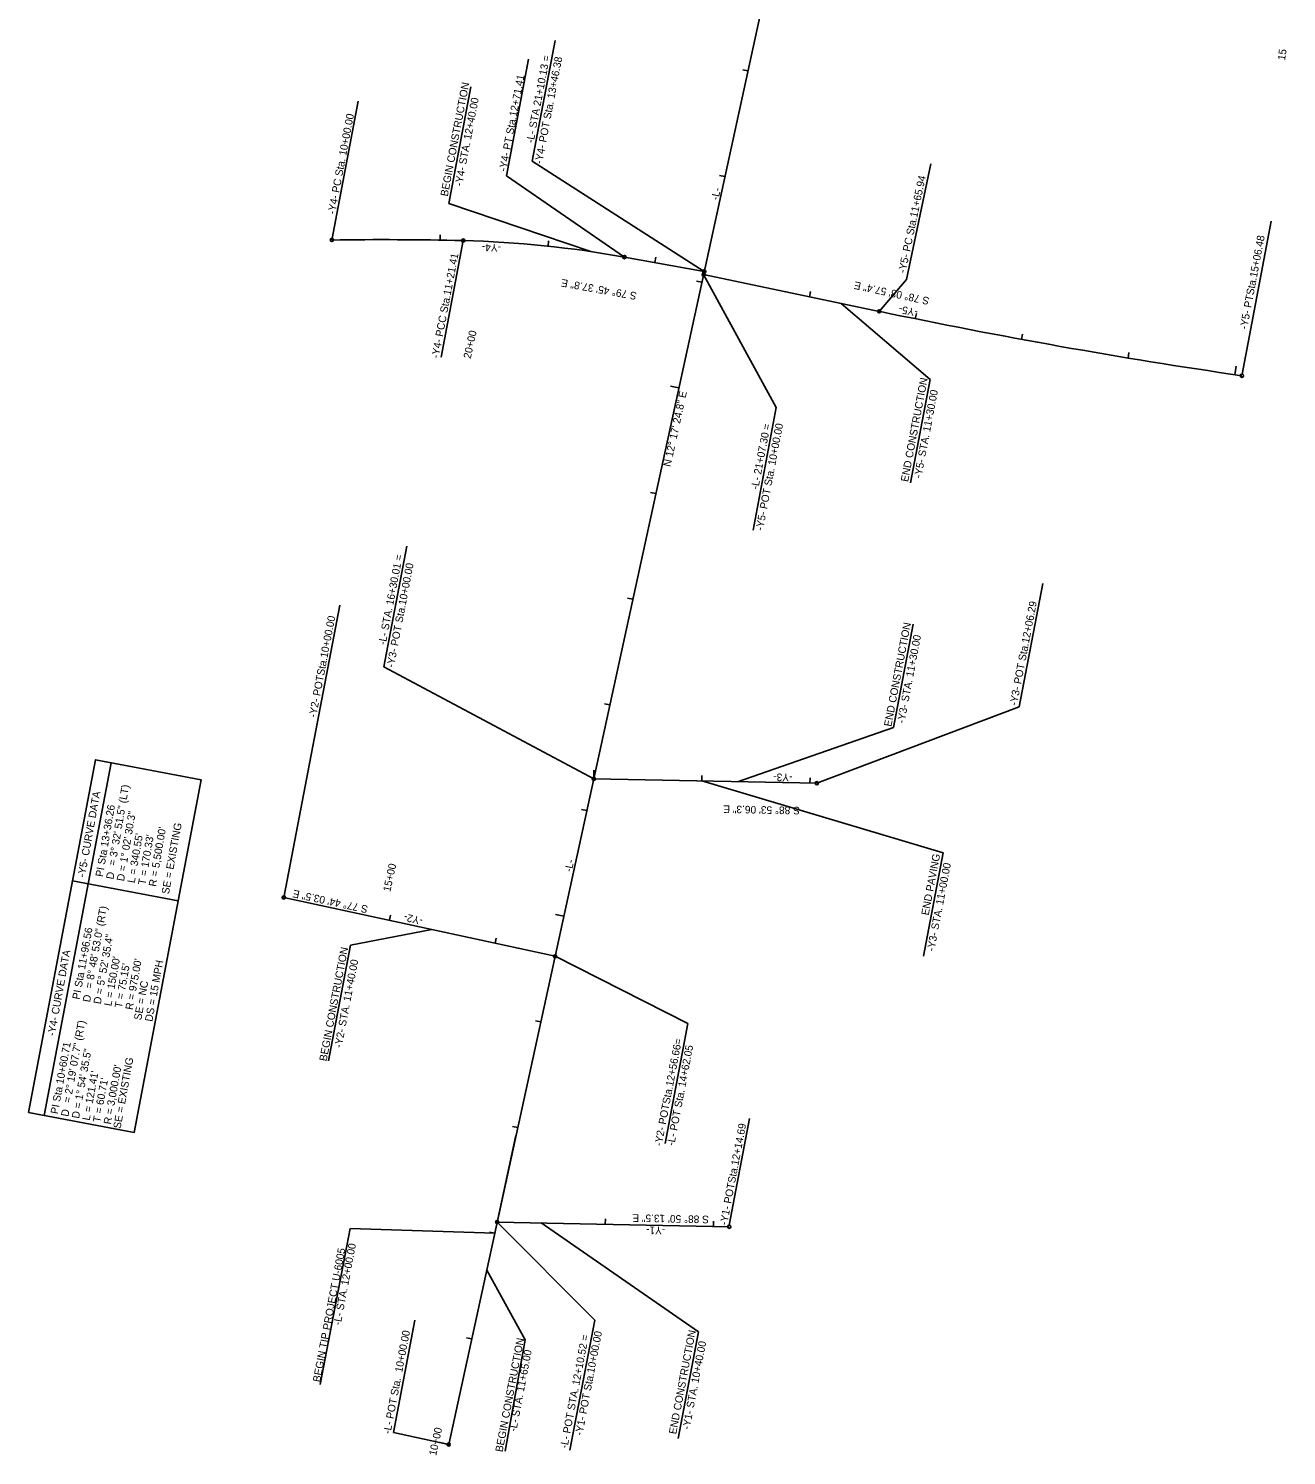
# Model space of a CAD drawing. Extents: x 1615712 to 1617175, y 899615 to 904865.
# Drawn here: x 1615800 to 1616963, y 899615 to 900935 of the extents above; entities that cross this region are included whole.
import ezdxf

# ---------------------------------------------------------------- set-up
doc = ezdxf.new("R2010")
doc.units = 0
for name, color, linetype in [('Prop Horizontal Alignment', 7, 'Continuous'), ('Prop Horizontal Alignment Curve and Spiral Data', 7, 'Continuous'), ('Prop Horizontal Alignment Direction Label', 7, 'Continuous'), ('Prop Horizontal Alignment Station Label', 7, 'Continuous'), ('Prop Horizontal Alignment Tick Label', 7, 'Continuous'), ('Prop Horizontal Alignment Tick Large', 7, 'Continuous'), ('Prop Horizontal Alignment Tick Small', 7, 'Continuous'), ('Scratch_Level_0', 7, 'Continuous')]:
    doc.layers.add(name, color=color, linetype=linetype)

msp = doc.modelspace()

# ---------------------------------------------------------------- linework, layer by layer
at = {"layer": 'Prop Horizontal Alignment'}
for p, q in [((1616188.3, 899625.3), (1616593.6, 901486.1)), ((1616188.3, 899625.3), (1616593.6, 901486.1)), ((1616230.8, 899820.7), (1616250.5, 899911)), ((1616233.1, 899831), (1616447.7, 899826.6))]:
    msp.add_line(p, q, dxfattribs=at)
at = {"layer": 'Prop Horizontal Alignment Curve and Spiral Data'}
for p, q in [((1615840.5, 900146.6), (1615938.3, 900128)), ((1616409.5, 900014.6), (1616388.5, 899903.7)), ((1616137.3, 899636.4), (1616157.1, 899740.3))]:
    msp.add_line(p, q, dxfattribs=at)
for points in [[(1615799.8, 899932.3), (1615861.8, 900258.5), (1615959.5, 900239.9), (1615897.6, 899913.8)], [(1615799.8, 899932.3), (1615861.8, 900258.5), (1615876.2, 900255.7), (1615814.3, 899929.6)]]:
    msp.add_lwpolyline(points, close=True, dxfattribs=at)
at = {"layer": 'Prop Horizontal Alignment Station Label'}
for p, q in [((1616265.4, 900812.1), (1616286.6, 900923.4)), ((1616241.6, 900798.3), (1616262.1, 900906.2)), ((1616188.3, 900772.8), (1616208.8, 900880.7)), ((1616080.6, 900740.5), (1616104.7, 900867.4)), ((1616265.4, 900812.1), (1616424.6, 900710)), ((1616611.5, 900702.5), (1616633.9, 900809.5)), ((1616350.8, 900723.3), (1616241.6, 900798.3)), ((1616188.3, 900772.8), (1616319.8, 900728.4)), ((1616921.8, 900615), (1616948.7, 900756.4)), ((1616181.2, 900630.7), (1616201.7, 900738.5)), ((1616350.8, 900723.3), (1616424.6, 900710)), ((1616350.8, 900723.3), (1616424.6, 900710)), ((1616491.2, 900584.1), (1616424, 900707.2)), ((1616424, 900707.2), (1616586.4, 900673.1)), ((1616586.4, 900673.1), (1616611.5, 900702.5)), ((1616633.5, 900610), (1616551.2, 900680.5)), ((1616615.3, 900514.5), (1616633.5, 900610)), ((1616469.8, 900470.9), (1616491.2, 900584.1)), ((1616128.4, 900344.5), (1616149.5, 900456)), ((1616715.6, 900307.5), (1616737.6, 900421.3)), ((1616036.1, 900132.7), (1616087.6, 900401.3)), ((1616599.5, 900288.3), (1616617.7, 900383.9)), ((1616128.4, 900344.5), (1616322.4, 900240.8)), ((1616715.6, 900307.5), (1616528.6, 900236.8)), ((1616599.5, 900288.3), (1616455.4, 900238.2)), ((1616322.4, 900240.8), (1616528.6, 900236.8)), ((1616645.5, 900172.4), (1616422.3, 900238.9)), ((1616627.3, 900076.9), (1616645.5, 900172.4)), ((1616035.8, 900131.2), (1616286.6, 900076.7)), ((1616097.5, 900087.1), (1616172.6, 900101.5)), ((1616077.2, 899980.2), (1616097.5, 900087.1)), ((1616286.6, 900076.7), (1616409.5, 900014.6)), ((1616447.7, 899828.1), (1616466.5, 899926.7)), ((1616323.3, 899740.4), (1616233.1, 899831)), ((1616419.1, 899729.5), (1616273.7, 899830.2)), ((1616259, 899722), (1616223.4, 899786.5)), ((1616300.4, 899620.2), (1616323.3, 899740.4)), ((1616400.4, 899631), (1616419.1, 899729.5)), ((1616240.5, 899619), (1616259, 899722)), ((1616186.8, 899625.6), (1616137.3, 899636.4))]:
    msp.add_line(p, q, dxfattribs=at)
msp.add_lwpolyline([(1616230.8, 899820.7), (1616097.2, 899825), (1616069.5, 899680.7)], dxfattribs=at)
for centre in [(1616080.3, 900739.1), (1616201.7, 900738.5), (1616350.8, 900723.3), (1616424, 900707.2), (1616424.6, 900710), (1616586.4, 900673.1), (1616921.6, 900613.5), (1616322.4, 900240.8), (1616528.6, 900236.8), (1616035.8, 900131.2), (1616286.6, 900076.7), (1616233.1, 899831), (1616447.7, 899826.6), (1616188.3, 899625.3)]:
    msp.add_circle(centre, 1.5, dxfattribs=at)
for centre, radius, start, end in [((1616127.1, 897739.4), 3000, 88.5752, 90.894), ((1616177.5, 899763.8), 975, 79.7605, 88.5752), ((1616177.5, 899763.8), 975, 79.7605, 88.5752), ((1617715.9, 906055.9), 5500, 258.1493, 261.6969), ((1617715.9, 906055.9), 5500, 258.1493, 261.6969)]:
    msp.add_arc(centre, radius, start, end, dxfattribs=at)
at = {"layer": 'Prop Horizontal Alignment Tick Large'}
for p, q in [((1616080.3, 900739.1), (1616081.8, 900746.9)), ((1616424, 900707.2), (1616425.6, 900715)), ((1616915.2, 900614.5), (1616916.4, 900622.4)), ((1616401.1, 900602.3), (1616393.3, 900604)), ((1616322.4, 900240.8), (1616322.5, 900248.8)), ((1616035.8, 900131.2), (1616037.3, 900139.1)), ((1616294.7, 900113.8), (1616286.9, 900115.5)), ((1616188.3, 899625.3), (1616180.4, 899627))]:
    msp.add_line(p, q, dxfattribs=at)
at = {"layer": 'Prop Horizontal Alignment Tick Small'}
for p, q in [((1616465, 900895.5), (1616460.1, 900896.5)), ((1616443.7, 900797.8), (1616438.8, 900798.8)), ((1616180.3, 900739), (1616180.4, 900744)), ((1616280.1, 900733.4), (1616280.6, 900738.4)), ((1616378.9, 900718.2), (1616379.8, 900723.1)), ((1616422.4, 900700.1), (1616417.5, 900701.1)), ((1616521.8, 900686.6), (1616522.9, 900691.5)), ((1616619.7, 900666.2), (1616620.7, 900671.1)), ((1616717.9, 900647.2), (1616718.8, 900652.1)), ((1616816.4, 900629.9), (1616817.2, 900634.9)), ((1616379.8, 900504.6), (1616374.9, 900505.7)), ((1616358.5, 900406.9), (1616353.7, 900408)), ((1616337.3, 900309.2), (1616332.4, 900310.3)), ((1616422.3, 900238.9), (1616422.4, 900243.9)), ((1616522.3, 900236.9), (1616522.4, 900241.9)), ((1616316, 900211.5), (1616311.1, 900212.6)), ((1616133.5, 900110), (1616134.6, 900114.9)), ((1616231.2, 900088.8), (1616232.3, 900093.6)), ((1616273.4, 900016.1), (1616268.5, 900017.2)), ((1616252.1, 899918.4), (1616247.2, 899919.4)), ((1616333, 899828.9), (1616333.2, 899833.9)), ((1616230.8, 899820.7), (1616225.9, 899821.7)), ((1616433, 899826.9), (1616433.1, 899831.9)), ((1616209.5, 899723), (1616204.7, 899724))]:
    msp.add_line(p, q, dxfattribs=at)
at = {"layer": 'Scratch_Level_0'}
for p, q in [((1616188.3, 899625.3), (1616593.6, 901486.1)), ((1616233.1, 899831), (1616447.7, 899826.6))]:
    msp.add_line(p, q, dxfattribs=at)

# ---------------------------------------------------------------- texts
at = {"layer": 'Prop Horizontal Alignment Curve and Spiral Data'}
for s, rotation, p in [('= 3%%d 32\' 51.5" (LT)', 80.3102, (1615880.2, 900160.2)), ('-Y5- CURVE DATA', 79.6716, (1615851.9, 900149.3)), ('PI Sta 13+36.26', 80.3102, (1615868.5, 900149.8)), ('D = 1%%d 02\' 30.3"', 80.3102, (1615888.1, 900145.8)), ("L = 340.55'", 80.3102, (1615898, 900144.1)), ("T = 170.33'", 80.3102, (1615907.9, 900142.4)), ("R = 5,500.00'", 80.3102, (1615917.7, 900140.8)), ('SE = EXISTING', 79.6716, (1615929.6, 900133.8)), ('D', 80.3102, (1615878.3, 900147.5)), ('= 8%%d 48\' 53.0" (RT)', 79.6721, (1615858.7, 900046.6)), ('PI Sta 11+96.56', 79.6721, (1615847, 900036.4)), ('D = 5%%d 52\' 35.4"', 79.6721, (1615866.6, 900032.1)), ('-Y4- CURVE DATA', 79.6716, (1615824.1, 900002.6)), ("L = 150.00'", 79.6721, (1615876.4, 900030.3)), ("R = 975.00'", 79.6721, (1615896.1, 900026.8)), ('DS = 15 MPH', 79.6716, (1615914.2, 900015.9)), ("T = 75.15'", 79.6721, (1615886.2, 900028.5)), ('SE = NC', 79.6716, (1615904, 900017.3)), ('D', 79.6721, (1615856.7, 900033.9)), ('= 2%%d 19\' 07.7" (RT)', 79.6716, (1615838.6, 899940.8)), ('PI Sta 10+60.71', 79.6716, (1615826.9, 899930.5)), ('D = 1%%d 54\' 35.5"', 79.6716, (1615846.5, 899926.3)), ('SE = EXISTING', 79.6716, (1615884.9, 899916.9)), ("L = 121.41'", 79.6716, (1615856.3, 899924.5)), ("R = 3,000.00'", 79.6716, (1615876, 899920.9)), ("T = 60.71'", 79.6716, (1615866.1, 899922.7)), ('D', 79.6716, (1615836.6, 899928.1))]:
    msp.add_text(s, height=7, rotation=rotation, dxfattribs=at).set_placement(p)
at = {"layer": 'Prop Horizontal Alignment Direction Label'}
for s, rotation, p in [('S 79%%d 45\' 37.8" E', 169.7605, (1616362.6, 900690.5)), ('S 78%%d 08\' 57.4" E', 167.719, (1616633.1, 900685.8)), ('N 12%%d 17\' 24.8" E', 77.7098, (1616393.4, 900528.9)), ('S 88%%d 53\' 06.3" E', 178.8851, (1616513, 900214.9)), ('S 77%%d 44\' 03.5" E', 167.7343, (1616114.1, 900123.3)), ('S 88%%d 50\' 13.5" E', 178.8371, (1616428.9, 899836.8))]:
    msp.add_text(s, height=7, rotation=rotation, dxfattribs=at).set_placement(p)
at = {"layer": 'Prop Horizontal Alignment Station Label'}
for s, rotation, p in [('-L- STA 21+10.13 =', 79.2494, (1616266.7, 900828.3)), ('-Y4- POT Sta. 13+46.38', 79.2494, (1616274.6, 900809)), ('-Y4- PT Sta.12+71.41', 79.2494, (1616241.5, 900802.1)), ('BEGIN CONSTRUCTION', 79.2494, (1616187.4, 900779)), ('-Y4- STA. 12+40.00', 79.2494, (1616200.7, 900788.5)), ('-Y4- PC Sta. 10+00.00', 79.2494, (1616083.2, 900762.4)), ('-Y5- PC Sta.11+65.94', 78.1493, (1616610.6, 900708)), ('-Y5- PTSta.15+06.48', 79.2494, (1616926.4, 900656)), ('-Y4- PCC Sta.11+21.41', 79.2494, (1616179, 900629.3)), ('END CONSTRUCTION', 79.2494, (1616613, 900515)), ('-Y5- STA. 11+30.00', 79.2494, (1616625.2, 900518.3)), ('-L- 21+07.30 =', 79.2494, (1616474.5, 900508.1)), ('-Y5- POT Sta. 10+00.00', 79.2494, (1616478.8, 900469.9)), ('-L- STA. 16+30.01 =', 79.2494, (1616130, 900364.2)), ('-Y3- POT Sta.10+00.00', 79.2494, (1616137.6, 900343.3)), ('-Y3- POT Sta.12+06.29', 79.0894, (1616713.6, 900308.1)), ('-Y2- POTSta.10+00.00', 79.1535, (1616065.6, 900297.1)), ('END CONSTRUCTION', 79.2494, (1616597.5, 900288.7)), ('-Y3- STA. 11+30.00', 79.2494, (1616609.6, 900291.7)), ('END PAVING', 79.2494, (1616632, 900114.2)), ('-Y3- STA. 11+00.00', 79.2494, (1616637.2, 900080.9)), ('BEGIN CONSTRUCTION', 79.2494, (1616075.4, 899979.3)), ('-Y2- STA. 11+40.00', 79.2494, (1616089.3, 899991.6)), ('-Y2- POTSta.12+56.66=', 79.2494, (1616385.2, 899900.8)), ('-L- POT Sta. 14+62.05', 79.2494, (1616396.8, 899901.2)), ('-Y1- POTSta.12+14.69', 79.2494, (1616445.6, 899827.7)), ('BEGIN TIP PROJECT U-6005', 79.2494, (1616069.4, 899682.6)), ('-L- STA. 12+00.00', 79.2494, (1616088.4, 899735.2)), ('-L- POT Sta.  10+00.00', 79.2494, (1616134.5, 899634.8)), ('-Y1- POT Sta.10+00.00', 79.2494, (1616311.8, 899633.1)), ('END CONSTRUCTION', 79.2494, (1616398.6, 899634.4)), ('BEGIN CONSTRUCTION', 79.2494, (1616238.1, 899617.9)), ('-L- POT STA. 12+10.52 =', 79.2494, (1616298, 899621.3)), ('-Y1- STA. 10+40.00', 79.2494, (1616411, 899638.7)), ('-L- STA. 11+65.00', 79.2494, (1616250.8, 899636.8))]:
    msp.add_text(s, height=7, rotation=rotation, dxfattribs=at).set_placement(p)
at = {"layer": 'Prop Horizontal Alignment Tick Label'}
for s, rotation, p in [('15', 81.6294, (1616961.5, 900904.9)), ('-L-', 77.7098, (1616437.6, 900775.5)), ('-Y4-', 178.5769, (1616236.7, 900735.3)), ('-Y5-', 168.742, (1616622.5, 900675.1)), ('20+00', 77.7098, (1616208.6, 900628.9)), ('-Y3-', 178.0747, (1616506.2, 900245.3)), ('-L-', 77.7098, (1616302, 900154.3)), ('15+00', 77.7098, (1616134.3, 900136)), ('-Y2-', 167.14, (1616164.9, 900112.5)), ('-Y1-', 179.3469, (1616388.5, 899826.6)), ('10+00', 77.7098, (1616176.7, 899614.5))]:
    msp.add_text(s, height=7, rotation=rotation, dxfattribs=at).set_placement(p)

doc.saveas('drawing.dxf')
